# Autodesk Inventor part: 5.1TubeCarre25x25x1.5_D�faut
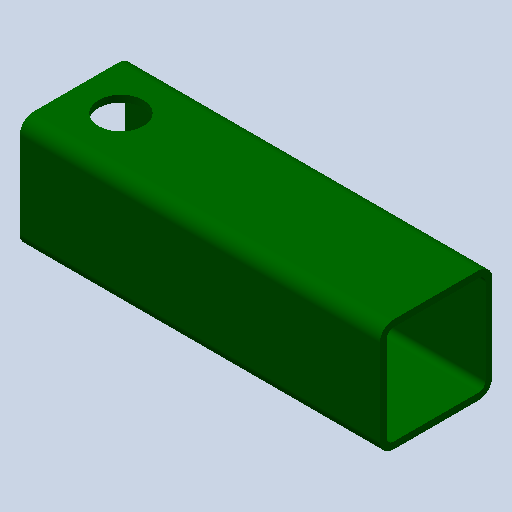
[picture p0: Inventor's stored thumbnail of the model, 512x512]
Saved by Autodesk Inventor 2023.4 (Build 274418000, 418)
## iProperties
Created: 2011-01
Part Number: 5.1TubeCarre25x25x1.5_D�faut
Document SubType Name: Modeling
Designer: eric
Density: 1 g/cm^3
Mass: 10.5809 g
Surface Area: 144.724 cm^2
Volume: 10.5809 cm^3
Material: Générique
Appearance: 0,128,0_1
Author: eric
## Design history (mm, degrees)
feature "Base1"
node "Corps solides"
node "Corps surfaciques"
node "Solide1"
